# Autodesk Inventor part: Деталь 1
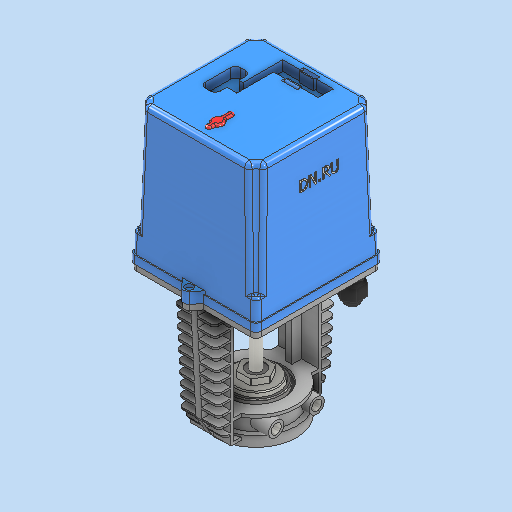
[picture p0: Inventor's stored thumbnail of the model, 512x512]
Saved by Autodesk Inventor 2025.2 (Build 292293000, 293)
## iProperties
Created: 2026-04
Part Number: Деталь 1
Material: Типовые
Document SubType Name: Modeling
Designer: igorr
Density: 1 g/cm^3
Appearance: По умолчанию
Author: igorr
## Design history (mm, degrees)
sketch "Эскиз1"
  geometry: L1 (-62.5, 62.5)-(-62.5, -62.5); L2 (-62.5, -62.5)-(62.5, -62.5); L3 (62.5, -62.5)-(62.5, 62.5); L4 (62.5, 62.5)-(-62.5, 62.5); L5 (-62.5, 62.5)-(62.5, -62.5); L6 (-62.5, -62.5)-(62.5, 62.5); L7 (0, 0)-(0, -71.5); L8 (0, -62.5)-(0, -71.5); L9 (0, 0)-(25.646, 0); L10 (0, -71.5)-(0, -61.5); C1 r 5 at (0, 66.5); 5 further points
  constraints: 20 end point, 6 midpoint, 2 parallel, 2 perpendicular, 2 point on line, 2 vertical, 1 centre point, 1 collinear, 1 symmetric about line, 4 other
  dimensions: "d0" = 125 distance of L1.start L1.end; "d1" = 125 distance of L2.end L1.end; "d2" = 71.5 distance of L7.start L7.end; "d5" = 10 distance of L7.end L10.end
extrude "Выдавливание1" new body sketch "Эскиз1" distance "d3" = 6; taper "d4" = 0 deg
chamfer "Фаска1" distance "d6" = 7.25; stored, may be unused: second distance "d7" = 2, angle "d8" = 45 deg
sketch "Эскиз2"
  geometry: L1 (-62.5, 62.5)-(-62.5, -62.5) reference; L2 (-62.5, -62.5)-(-10.25, -62.5) reference; L3 (-3.841, -69.701)-(-10.25, -62.5) reference; L4 (10.25, -62.5)-(3.841, -69.701) reference; L5 (10.25, -62.5)-(62.5, -62.5) reference; L6 (62.5, -62.5)-(62.5, 62.5) reference; L7 (62.5, 62.5)-(10.25, 62.5) reference; L8 (3.841, 69.701)-(10.25, 62.5) reference; L9 (-10.25, 62.5)-(-3.841, 69.701) reference; L10 (-10.25, 62.5)-(-62.5, 62.5) reference; L11 (61.5, 61.5)-(61.5, -61.5); L12 (61.5, -61.5)-(9.801, -61.5); L13 (9.801, -61.5)-(3.083, -69.049); L14 (-3.083, -69.049)-(-9.801, -61.5); L15 (-9.801, -61.5)-(-61.5, -61.5); L16 (-61.5, -61.5)-(-61.5, 61.5); L17 (-61.5, 61.5)-(-9.801, 61.5); L18 (-9.801, 61.5)-(-3.083, 69.049); L19 (3.083, 69.049)-(9.801, 61.5); L20 (9.801, 61.5)-(61.5, 61.5); A1 r 5 centre (0, -66.5) between (-3.841, -69.701) and (3.841, -69.701) reference; A2 r 5 centre (0, 66.5) between (3.841, 69.701) and (-3.841, 69.701) reference; A3 r 4 centre (0, -66.5) between (-3.083, -69.049) and (3.083, -69.049); A4 r 4 centre (0, 66.5) between (3.083, 69.049) and (-3.083, 69.049); 1 further point
  constraints: 20 end point, 4 point on circle, 2 centre point, 11 other
  dimensions: "d9" = 1 distance between parallel lines of L6 L11
extrude "Выдавливание2" cut sketch "Эскиз2" distance "d10" = 21; taper "d11" = 0 deg
sketch "Эскиз3"
  geometry: L1 (61.5, 61.5)-(9.801, 61.5) reference; L2 (9.801, 61.5)-(3.083, 69.049) reference; L3 (-3.083, 69.049)-(-9.801, 61.5) reference; L4 (-9.801, 61.5)-(-61.5, 61.5) reference; L5 (-61.5, 61.5)-(-61.5, -61.5) reference; L6 (-61.5, -61.5)-(-9.801, -61.5) reference; L7 (-9.801, -61.5)-(-3.083, -69.049) reference; L8 (3.083, -69.049)-(9.801, -61.5) reference; L9 (9.801, -61.5)-(61.5, -61.5) reference; L10 (61.5, -61.5)-(61.5, 61.5) reference; L11 (62.5, -62.5)-(10.25, -62.5); L12 (10.25, -62.5)-(3.841, -69.701); L13 (-3.841, -69.701)-(-10.25, -62.5); L14 (-10.25, -62.5)-(-62.5, -62.5); L15 (-62.5, -62.5)-(-62.5, 62.5); L16 (-62.5, 62.5)-(-10.25, 62.5); L17 (-10.25, 62.5)-(-3.841, 69.701); L18 (3.841, 69.701)-(10.25, 62.5); L19 (10.25, 62.5)-(62.5, 62.5); L20 (62.5, 62.5)-(62.5, -62.5); A1 r 4 centre (0, 66.5) between (3.083, 69.049) and (-3.083, 69.049) reference; A2 r 4 centre (0, -66.5) between (-3.083, -69.049) and (3.083, -69.049) reference; A3 r 5 centre (0, -66.5) between (-3.841, -69.701) and (3.841, -69.701); A4 r 5 centre (0, 66.5) between (3.841, 69.701) and (-3.841, 69.701); 1 further point
  constraints: 20 end point, 4 point on circle, 2 centre point, 11 other
  dimensions: "d12" = 1 distance between parallel lines of L9 L11
extrude "Выдавливание3" join sketch "Эскиз3" distance "d13" = 8; taper "d14" = 0 deg
sketch "Эскиз4"
  geometry: L1 (61.5, -61.5)-(61.5, 61.5); L2 (61.5, 61.5)-(-61.5, 61.5); L3 (-61.5, 61.5)-(-61.5, -61.5); L4 (-61.5, -61.5)-(61.5, -61.5); L5 (61.5, -61.5)-(-61.5, 61.5); L6 (61.5, 61.5)-(-61.5, -61.5); 1 further point
  constraints: 12 end point, 2 midpoint, 2 parallel, 1 perpendicular, 1 vertical
  dimensions: "d15" = 123 distance of L1.start L1.end; "d16" = 123 distance of L2.end L1.end
extrude "Выдавливание4" join sketch "Эскиз4" distance "d17" = 130; taper "d18" = -1 deg
sketch "Эскиз5"
  geometry: L1 (61.5, 61.5)-(61.5, -61.5) reference; L2 (61.5, -61.5)-(-61.5, -61.5) reference; L3 (-61.5, -61.5)-(-61.5, 61.5) reference; L4 (-61.5, 61.5)-(61.5, 61.5) reference; L5 (-3.841, 69.701)-(-10.25, 62.5) reference; L6 (-10.25, 62.5)-(-62.5, 62.5) reference; L7 (-62.5, 62.5)-(-62.5, -62.5) reference; L8 (-62.5, -62.5)-(-10.25, -62.5) reference; L9 (-10.25, -62.5)-(-3.841, -69.701) reference; L10 (3.841, -69.701)-(10.25, -62.5) reference; L11 (10.25, -62.5)-(62.5, -62.5) reference; L12 (62.5, -62.5)-(62.5, 62.5) reference; L13 (62.5, 62.5)-(10.25, 62.5) reference; L14 (10.25, 62.5)-(3.841, 69.701) reference; L15 (10.25, 62.5)-(14.397, 57.84); L16 (14.397, 57.84)-(-14.397, 57.84); L17 (-14.397, 57.84)-(-10.25, 62.5); L18 (62.5, 0)-(81.182, 0); L19 (10.25, -62.5)-(3.841, -69.701); L20 (-3.841, -69.701)-(-10.25, -62.5); L21 (14.397, -57.84)-(-14.397, -57.84); L22 (10.25, -62.5)-(14.397, -57.84); L23 (-14.397, -57.84)-(-10.25, -62.5); C1 r 4 at (0, 66.101); C2 r 4 at (0, -66.101); A1 r 5 centre (0, -66.5) between (-3.841, -69.701) and (3.841, -69.701) reference; A2 r 5 centre (0, 66.5) between (3.841, 69.701) and (-3.841, 69.701) reference; A3 r 5 centre (0, -66.5) between (-3.841, -69.701) and (3.841, -69.701); 1 further point
  constraints: 18 end point, 4 symmetric about line, 3 centre point, 2 horizontal, 2 point on circle, 2 point on line, 1 collinear, 1 midpoint, 2 other
  dimensions: "d19" = 8 diameter of C1
extrude "Выдавливание5" join sketch "Эскиз5" distance "d20" = 3; taper "d21" = 0 deg
sketch "Эскиз6"
  geometry: L1 (-59.231, 59.231)-(59.231, 59.231) reference; C1 r 7.5 at (59.231, 59.231); C2 r 7.5 at (-59.231, 59.231); C3 r 7.5 at (-59.231, -59.231); C4 r 7.5 at (59.231, -59.231); 1 further point
  constraints: 4 centre point, 9 other
  dimensions: "d22" = 15 diameter of C1; "d25" = 360 deg dimension on point (0, 0) L1.end (derived)
extrude "Выдавливание6" cut sketch "Эскиз6" distance "d27" = 110; taper "d28" = -2 deg
sketch "Эскиз7"
  geometry: L1 (-21.282, 47.681)-(28.718, 47.681); L2 (28.718, 47.681)-(28.718, 32.681); L3 (28.718, 32.681)-(-21.282, 32.681); L4 (-21.282, 32.681)-(-21.282, 47.681); L5 (-21.282, 47.681)-(28.718, 32.681); L6 (28.718, 47.681)-(-21.282, 32.681); L7 (-40.282, 15)-(-40.282, -10); L8 (-35.282, -15)-(-30.282, -15); L9 (-25.282, -10)-(-25.282, 15); L10 (-30.282, 20)-(-35.282, 20); L11 (-40.282, 20)-(-25.282, -15); L12 (-40.282, -15)-(-25.282, 20); L13 (-35.282, 8.5)-(-15.282, 8.5); L14 (-15.282, 8.5)-(-15.282, -3.5); L15 (-15.282, -3.5)-(-35.282, -3.5); L16 (-35.282, -3.5)-(-35.282, 8.5); L17 (-35.282, 8.5)-(-15.282, -3.5); L18 (-15.282, 8.5)-(-35.282, -3.5); L19 (-15.282, -3.5)-(-21.282, -3.5); L20 (-21.282, -3.5)-(-21.282, 50.128); L21 (-21.282, 50.128)-(-15.282, 50.128); L22 (-15.282, 50.128)-(-15.282, -3.5); L23 (-4.282, 51.181)-(-4.282, 29.181); L24 (-4.282, 29.181)-(11.718, 29.181); L25 (11.718, 29.181)-(11.718, 51.181); L26 (11.718, 51.181)-(-4.282, 51.181); L27 (-4.282, 51.181)-(11.718, 29.181); L28 (-4.282, 29.181)-(11.718, 51.181); A1 r 5 centre (-30.282, 15) between (-25.282, 15) and (-30.282, 20); A2 r 5 centre (-30.282, -10) between (-30.282, -15) and (-25.282, -10); A3 r 5 centre (-35.282, -10) between (-40.282, -10) and (-35.282, -15); A4 r 5 centre (-35.282, 15) between (-35.282, 20) and (-40.282, 15); 14 further points
  constraints: 56 end point, 10 parallel, 9 midpoint, 9 point on line, 8 point on circle, 8 tangent, 5 perpendicular, 4 centre point, 3 equal radius, 2 horizontal, 2 vertical, 1 collinear
  dimensions: "d29" = 50 distance of L1.start L1.end; "d30" = 15 distance of L1.end L2.end; "d31" = 35 distance of L11.start L12.start; "d32" = 15 distance of L11.end L12.start; "d33" = 20 distance of L13.start L13.end; "d34" = 12 distance of L13.end L14.end; "d35" = 6 distance of L14.end L19.end; "d36" = 22 distance of L23.start L23.end; "d37" = 16 distance of L24.end L23.end; "d38" = 5 radius of A1
extrude "Выдавливание7" cut sketch "Эскиз7" distance "d39" = 10; taper "d40" = 0 deg
sketch "Эскиз8"
  geometry: L1 (0, -46.285)-(0, -25.359); L2 (-15.282, 32.681)-(-15.282, -3.5) reference; L3 (3, -46.285)-(3, -25.359); L4 (-3, -25.359)-(-3, -46.285); C1 r 6 at (0, -38.032); A1 r 3 centre (0, -46.285) between (-3, -46.285) and (3, -46.285); A2 r 3 centre (0, -25.359) between (3, -25.359) and (-3, -25.359); 6 further points
  constraints: 8 end point, 4 point on circle, 4 tangent, 3 centre point, 2 parallel, 1 midpoint
  dimensions: "d41" = 12 diameter of C1; "d42" = 6 diameter of A2
extrude "Выдавливание8" join sketch "Эскиз8" distance "d43" = 2; taper "d44" = 0 deg
sketch "Эскиз9"
  geometry: L1 (-4.282, 51.181)-(11.718, 51.181) reference; L2 (11.718, 29.181)-(-4.282, 29.181) reference; L3 (11.718, 51.181)-(-4.282, 29.181); L4 (-3.282, 49.181)-(-3.282, 31.181); L5 (-3.282, 31.181)-(10.718, 31.181); L6 (10.718, 31.181)-(10.718, 49.181); L7 (10.718, 49.181)-(-3.282, 49.181); L8 (-3.282, 49.181)-(10.718, 31.181); L9 (-3.282, 31.181)-(10.718, 49.181); L10 (-3.282, 46.181)-(10.718, 46.181); L11 (10.718, 46.181)-(10.718, 34.181); L12 (10.718, 34.181)-(-3.282, 34.181); L13 (-3.282, 34.181)-(-3.282, 46.181); L14 (-3.282, 46.181)-(10.718, 34.181); L15 (10.718, 46.181)-(-3.282, 34.181); 6 further points
  constraints: 26 end point, 5 midpoint, 4 parallel, 2 perpendicular, 1 vertical
  dimensions: "d45" = 18 distance of L4.start L4.end; "d46" = 14 distance of L5.end L4.end; "d47" = 12 distance of L10.end L11.end
extrude "Выдавливание9" join sketch "Эскиз9" stored distance "d48" = 2; taper "d49" = 0 deg
sketch "Эскиз11"
  geometry: C1 r 22.5 at (0, 0); C2 r 25 at (0, 0); 1 further point
  constraints: 2 centre point, 1 coincident
  dimensions: "d50" = 45 diameter of C1; "d51" = 2.5 radial gap between concentric circles of C1 C2
extrude "Выдавливание10" cut sketch "Эскиз11" distance "d52" = 10; taper "d53" = 0 deg
sketch "Эскиз12"
  geometry: L1 (3, -61.5)-(3, 61.5); L2 (3, 61.5)-(-3, 61.5); L3 (-3, 61.5)-(-3, -61.5); L4 (-3, -61.5)-(3, -61.5); L5 (3, -61.5)-(-3, 61.5); L6 (3, 61.5)-(-3, -61.5); L7 (-9.801, 61.5)-(-61.5, 61.5) reference; L8 (3, -32.5)-(-3, -32.5); L9 (-3, -32.5)-(-3, 32.5); L10 (-3, 32.5)-(3, 32.5); L11 (3, 32.5)-(3, -32.5); L12 (3, -32.5)-(-3, 32.5); L13 (-3, -32.5)-(3, 32.5); L14 (20, -45.032)-(-20, -45.032); L15 (-20, -45.032)-(-20, -42.032); L16 (-20, -42.032)-(20, -42.032); L17 (20, -42.032)-(20, -45.032); L18 (20, -45.032)-(-20, -42.032); L19 (-20, -45.032)-(20, -42.032); L20 (-3, 0)-(-7.639, 0); L21 (20, 42.032)-(20, 45.032); L22 (-20, 42.032)-(20, 42.032); L23 (-20, 45.032)-(20, 42.032); L24 (20, 45.032)-(-20, 42.032); L25 (20, 45.032)-(-20, 45.032); L26 (-20, 45.032)-(-20, 42.032); 15 further points
  constraints: 50 end point, 9 midpoint, 7 parallel, 5 symmetric about line, 3 perpendicular, 2 collinear, 1 horizontal
  dimensions: "d54" = 6 distance of L2.end L1.end; "d55" = 65 distance of L8.end L9.end; "d58" = 40 distance of L14.start L14.end; "d59" = 3 distance of L14.end L15.end
extrude "Выдавливание11" join sketch "Эскиз12" distance "d56" = 120; taper "d57" = 0 deg
sketch "Эскиз13"
  geometry: C1 r 25 at (0, 0) reference; C2 r 40 at (0, 0); 1 further point
  constraints: 1 centre point, 1 coincident
  dimensions: "d60" = 80 diameter of C2
extrude "Выдавливание12" join sketch "Эскиз13" stored distance "d61" = 10; taper "d63" = 0 deg; dims "d62" = 2, "d64" = 0
sketch "Эскиз14"
  geometry: C1 r 40 at (0, 0) reference; C2 r 35 at (0, 0); 1 further point
  constraints: 1 centre point, 1 coincident
  dimensions: "d65" = 70 diameter of C2
extrude "Выдавливание13" join sketch "Эскиз14" distance "d66" = 15; taper "d67" = 0 deg
sketch "Эскиз15"
  geometry: L1 (-20, 42.032)-(-20, -42.032); L2 (-20, -42.032)-(20, -42.032); L3 (20, -42.032)-(20, 42.032); L4 (20, 42.032)-(-20, 42.032); L5 (-20, 42.032)-(20, -42.032); L6 (-20, -42.032)-(20, 42.032); L7 (3, -42.032)-(20, -42.032) reference; C1 r 40 at (0, 0); C2 r 27.5 at (0, 0); A1 r 40 centre (0, 0) between (3, -39.887) and (3, 39.887) reference; 5 further points
  constraints: 12 end point, 2 centre point, 2 coincident, 2 midpoint, 2 parallel, 1 collinear, 1 concentric, 1 perpendicular, 1 vertical
  dimensions: "d68" = 40 distance of L2.end L1.end; "d69" = 55 diameter of C2
extrude "Выдавливание14" join sketch "Эскиз15" distance "d70" = 3; taper "d71" = 0 deg
sketch "Эскиз16"
  geometry: L1 (20, 42.032)-(20, -42.032); L2 (20, -42.032)-(-20, -42.032); L3 (-20, -42.032)-(-20, 42.032); L4 (-20, 42.032)-(20, 42.032); L5 (20, 42.032)-(-20, -42.032); L6 (20, -42.032)-(-20, 42.032); A1 r 40 centre (0, 0) between (-20, 34.641) and (-20, -34.641) reference; 1 further point
  constraints: 12 end point, 2 midpoint, 2 parallel, 1 perpendicular, 1 vertical
extrude "Выдавливание15" join sketch "Эскиз16" distance "d72" = 3; taper "d73" = 0 deg
sketch "Эскиз17"
  geometry: L1 (0, -61.5)-(-120, -61.5) reference; L2 (0, -61.5)-(-9, -61.5); L3 (0, -42.032)-(-97, -42.032) reference; L4 (-9, -61.5)-(-9, -42.032); L5 (-9, -42.032)-(-11, -42.032); L6 (-11, -42.032)-(-11, -61.5); L7 (-11, -61.5)-(-9, -61.5); 3 further points
  constraints: 10 end point, 2 parallel, 2 point on line, 1 perpendicular, 1 vertical
  dimensions: "d74" = 9 distance of L1.start L2.end; "d75" = 2 distance of L5.end L4.end
extrude "Выдавливание16" join sketch "Эскиз17" stored distance "d76" = 40; taper "d77" = 0 deg
pattern_linear "Прямоуг.массив1"
mirror "Зеркальное отражение1"
sketch "Эскиз18"
  geometry: L1 (10.391, 0)-(0, 0) reference; L2 (0, 0)-(-11.293, 18.805); L3 (-16.468, 120)-(-16.468, 111) reference; L4 (-11.293, 18.805)-(-16.468, 120); L5 (0, 0)-(-16.468, 0) reference; L6 (-16.468, 120)-(-16.468, 0); L7 (-16.468, 0)-(0, 0); L8 (45.032, 120)-(45.032, 160.583); L9 (79.673, 0)-(90.064, 0); L10 (90.064, 0)-(101.357, 18.805); L11 (106.532, 120)-(106.532, 111); L12 (101.357, 18.805)-(106.532, 120); L13 (90.064, 0)-(106.532, 0); L14 (106.532, 120)-(106.532, 0); L15 (106.532, 0)-(90.064, 0); 2 further points
  constraints: 24 end point, 6 symmetric about line, 2 perpendicular, 1 vertical
extrude "Выдавливание17" cut sketch "Эскиз18" distance "d81" = 40; taper "d82" = 0 deg
sketch "Эскиз19"
  geometry: C1 r 27.5 at (0, 0) reference; C2 r 21 at (0, 0); 1 further point
  constraints: 1 centre point, 1 coincident
  dimensions: "d83" = 42 diameter of C2
extrude "Выдавливание18" join sketch "Эскиз19" distance "d84" = 9; taper "d85" = 0 deg
sketch "Эскиз20"
  geometry: L1 (14.383, 0)-(7.192, -12.456); L2 (7.192, -12.456)-(-7.192, -12.456); L3 (-7.192, -12.456)-(-14.383, 0); L4 (-14.383, 0)-(-7.192, 12.456); L5 (-7.192, 12.456)-(7.192, 12.456); L6 (7.192, 12.456)-(14.383, 0); 2 further points
  constraints: 12 end point, 1 coincident, 13 other
extrude "Выдавливание19" join sketch "Эскиз20" distance "d86" = 6; taper "d87" = 0 deg
sketch "Эскиз21"
  geometry: C1 r 9 at (0, 0); 1 further point
  constraints: 1 centre point, 1 coincident
  dimensions: "d88" = 18 diameter of C1
extrude "Выдавливание20" cut sketch "Эскиз21" distance "d89" = 1; taper "d90" = 0 deg
sketch "Эскиз22"
  geometry: C1 r 5 at (0, 0); 1 further point
  constraints: 1 centre point, 1 coincident
  dimensions: "d91" = 10 diameter of C1
extrude "Выдавливание21" join sketch "Эскиз22" distance "d92" = 48; taper "d93" = 0 deg
sketch "Эскиз23"
  geometry: C1 r 6.5 at (0, 0); 1 further point
  constraints: 1 centre point, 1 coincident
  dimensions: "d94" = 13 diameter of C1
extrude "Выдавливание22" join sketch "Эскиз23" distance "d95" = 15; taper "d96" = 0 deg
sketch "Эскиз24"
  geometry: L1 (-15.09, -15)-(-31.84, -15); L2 (-31.84, -15)-(-31.84, 15); L3 (-31.84, 15)-(-15.09, 15); L4 (-15.09, 15)-(-15.09, -15); L5 (-23, -6.5)-(-23, 6.5) reference; L6 (-15.09, -15)-(-31.84, 15); L7 (-31.84, -15)-(-15.09, 15); 2 further points
  constraints: 12 end point, 3 parallel, 2 midpoint, 1 perpendicular
  dimensions: "d97" = 30 distance of L1.end L2.end
extrude "Выдавливание23" join sketch "Эскиз24" stored distance "d98" = 8; taper "d99" = 0 deg
sketch "Эскиз25"
  geometry: L1 (-0.5, 21)-(8.5, 21); L2 (8.5, 21)-(8.5, 9); L3 (8.5, 9)-(-0.5, 9); L4 (-0.5, 9)-(-0.5, 21); L5 (-0.5, 21)-(8.5, 9); L6 (8.5, 21)-(-0.5, 9); A1 r 6.5 centre (4, 15) between (0, 20.123) and (0, 9.877) reference; 1 further point
  constraints: 12 end point, 2 midpoint, 2 parallel, 1 horizontal, 1 perpendicular
  dimensions: "d100" = 9 distance of L1.start L1.end; "d101" = 12 distance of L1.end L2.end
extrude "Выдавливание24" join sketch "Эскиз25" distance "d102" = 15; taper "d103" = 0 deg
sketch "Эскиз26"
  geometry: L1 (-1, -2.664)-(13, -2.664); L2 (13, -2.664)-(13, 4.336); L3 (6, 11.336)-(6, 11.336); L4 (-1, 4.336)-(-1, -2.664); L5 (-1, -2.664)-(13, 11.336); L6 (13, -2.664)-(-1, 11.336); A1 r 7 centre (6, 4.336) between (6, 11.336) and (-1, 4.336); A2 r 7 centre (6, 4.336) between (13, 4.336) and (6, 11.336); 3 further points
  constraints: 12 end point, 4 point on circle, 4 point on line, 4 tangent, 2 centre point, 2 midpoint, 2 parallel, 1 concentric, 1 horizontal, 1 perpendicular
  dimensions: "d104" = 14 distance of L1.start L1.end; "d105" = 14 distance of L5.end L1.end; "d106" = 7 radius of A1
extrude "Выдавливание25" join sketch "Эскиз26" distance "d107" = 2; taper "d108" = 0 deg
sketch "Эскиз27"
  geometry: L1 (-7, -17.754)-(7, -17.754) reference; L2 (-7, -17.754)-(7, -17.754); L3 (7, -17.754)-(7, -15.09); L4 (7, -15.09)-(-7, -15.09); L5 (-7, -15.09)-(-7, -17.754); 1 further point
  constraints: 8 end point, 3 equal length, 1 perpendicular
extrude "Выдавливание26" join sketch "Эскиз27" stored distance "d109" = 2; taper "d110" = 0 deg
mirror "Зеркальное отражение2"
sketch "Эскиз31"
  geometry: L1 (-100, -34.871)-(-115, -34.871) reference; L2 (-107.5, -34.871)-(-107.5, 34.871); L3 (-100, 34.871)-(-115, 34.871) reference; C1 r 7.5 at (-107.5, 0); C2 r 5 at (-107.5, 0); 1 further point
  constraints: 3 midpoint, 2 centre point, 2 end point, 1 coincident
  dimensions: "d117" = 10 diameter of C2
extrude "Выдавливание30" join sketch "Эскиз31" distance "d118" = 40; taper "d119" = 0 deg
sketch "Эскиз32"
  geometry: L1 (-100, 34.871)-(-115, 34.871) reference; L2 (-107.5, 34.871)-(-107.5, -34.871); L3 (-115, -34.871)-(-100, -34.871) reference; L4 (-100, 0)-(-100, 34.871) reference; L5 (-97, 27.5)-(-97, -27.5) reference; L6 (-97, 0)-(-91.595, 0); C1 r 7.5 at (-107.5, 20.02); C2 r 5 at (-107.5, 20.02); C3 r 7.5 at (-107.5, -20.02); C4 r 5 at (-107.5, -20.02); 1 further point
  constraints: 4 centre point, 4 end point, 4 midpoint, 2 coincident, 2 symmetric about line, 1 horizontal, 1 point on line, 1 tangent, 2 other
  dimensions: "d120" = 10 diameter of C2
extrude "Выдавливание31" join sketch "Эскиз32" distance "d121" = 40; taper "d122" = 0 deg
sketch "Эскиз33"
  geometry: L1 (58.359, -47.515)-(52.809, -56.952); L2 (52.809, -56.952)-(41.862, -56.863); L3 (41.862, -56.863)-(36.465, -47.338); L4 (36.465, -47.338)-(42.015, -37.902); L5 (42.015, -37.902)-(52.963, -37.991); L6 (52.963, -37.991)-(58.359, -47.515); L7 (45.512, 27.742)-(45.512, 7.03); L8 (45.512, 7.03)-(57.512, 7.03); L9 (57.512, 7.03)-(57.512, 27.742); L10 (57.512, 27.742)-(45.512, 27.742); L11 (45.512, 27.742)-(57.512, 7.03); L12 (45.512, 7.03)-(57.512, 27.742); C1 r 10 at (47.412, 43.457); 3 further points
  constraints: 24 end point, 2 midpoint, 2 parallel, 1 centre point, 1 perpendicular, 1 vertical, 13 other
  dimensions: "d123" = 20 diameter of C1; "d124" = 12 distance of L8.end L7.end
extrude "Выдавливание32" join sketch "Эскиз33" distance "d125" = 3; taper "d126" = 0 deg
node "Непосредственное редактирование1"
sketch "Эскиз34"
  geometry: L1 (10.948, 0)-(0, 0) reference; L2 (10.948, -18.962)-(0, -18.962) reference; L3 (10.948, 0)-(0, -18.962); C1 r 7.5 at (5.474, -9.481); 1 further point
  constraints: 2 end point, 1 centre point, 1 midpoint
  dimensions: "d130" = 15 diameter of C1
extrude "Выдавливание33" join sketch "Эскиз34" distance "d131" = 5; taper "d132" = 0 deg
sketch "Эскиз35"
  geometry: L1 (9.679, -5.536)-(0.046, -11.15); L2 (0.046, -11.15)-(-9.634, -5.615); L3 (-9.634, -5.615)-(-9.679, 5.536); L4 (-9.679, 5.536)-(-0.046, 11.15); L5 (-0.046, 11.15)-(9.634, 5.615); L6 (9.634, 5.615)-(9.679, -5.536); C1 r 7.5 at (0, 0) reference; 2 further points
  constraints: 12 end point, 1 coincident, 13 other
extrude "Выдавливание34" join sketch "Эскиз35" distance "d133" = 12; taper "d134" = 0 deg
sketch "Эскиз36"
  geometry: C1 r 9 at (0, 0); C2 r 7.5 at (0, 0) reference; C3 r 4 at (0, 0); 1 further point
  constraints: 2 centre point, 1 coincident
  dimensions: "d135" = 18 diameter of C1; "d136" = 8 diameter of C3
extrude "Выдавливание35" join sketch "Эскиз36" distance "d137" = 8; taper "d138" = 0 deg
sketch "Эскиз37"
  geometry: L1 (43.658, 99.007)-(55.919, 99.007); L2 (55.919, 99.007)-(55.919, 95.895); L3 (55.919, 95.895)-(43.658, 95.895); L4 (43.658, 95.895)-(43.658, 99.007); 1 further point
  constraints: 2 other
feature "Рельеф1" sketch "Эскиз37" dims "d139" = 0.5, "d140" = 0
fillet "Сопряжение1" dims "d145" = 5
fillet "Сопряжение2" dims "d146" = 2
fillet "Сопряжение3" dims "d147" = 4
fillet "Сопряжение4" dims "d148" = 2
sketch "Эскиз40"
  geometry: C1 r 2.5 at (-10.754, 0); A1 r 7 centre (-10.754, 0) between (-10.754, -7) and (-10.754, 7) reference; 1 further point
  constraints: 1 centre point, 1 coincident
  dimensions: "d149" = 5 diameter of C1
extrude "Выдавливание38" join sketch "Эскиз40" stored distance "d150" = 25; taper "d151" = 0 deg
sketch "Эскиз41"
  geometry: L1 (5, -38)-(-5, -38) reference; L2 (0, -38)-(0, -34.078); C1 r 3 at (-10.058, -24.967); C2 r 3 at (10.058, -24.967); 1 further point
  constraints: 2 centre point, 2 end point, 1 midpoint, 1 symmetric about line, 1 vertical, 1 other
  dimensions: "d152" = 6 diameter of C1
extrude "Выдавливание39" cut sketch "Эскиз41" stored distance "d153" = 25; taper "d154" = 0 deg
sketch "Эскиз42"
  geometry: C1 r 27.5 at (0, 0) reference; 1 further point
extrude "Выдавливание40" cut sketch "Эскиз42" distance "d155" = 3; taper "d156" = 0 deg
chamfer "Фаска2" distance "d161" = 1; stored, may be unused: second distance "d162" = 2, angle "d163" = 45 deg
sketch "Эскиз44"
  geometry: C1 r 21 at (0, 0) reference; C2 r 25 at (0, 0); C3 r 22 at (0, 0); 1 further point
  constraints: 2 centre point
  dimensions: "d164" = 4 radial gap between concentric circles of C1 C2; "d165" = 1 radial gap between concentric circles of C1 C3
extrude "Выдавливание42" join sketch "Эскиз44" distance "d166" = 5; taper "d167" = 0 deg
fillet "Сопряжение6" dims "d168" = 1
fillet "Сопряжение7" dims "d169" = 1
node "Твердое тело1"
node "Спроецированная петля1"
node "Спроецированная петля2"
node "Спроецированная петля3"
node "Эскиз — круговой массив1" dims "d25" = 360 deg (derived)
feature "Перенос1" dims "d129" = 2
other parameters: "d127" = 0, "d128" = 0
